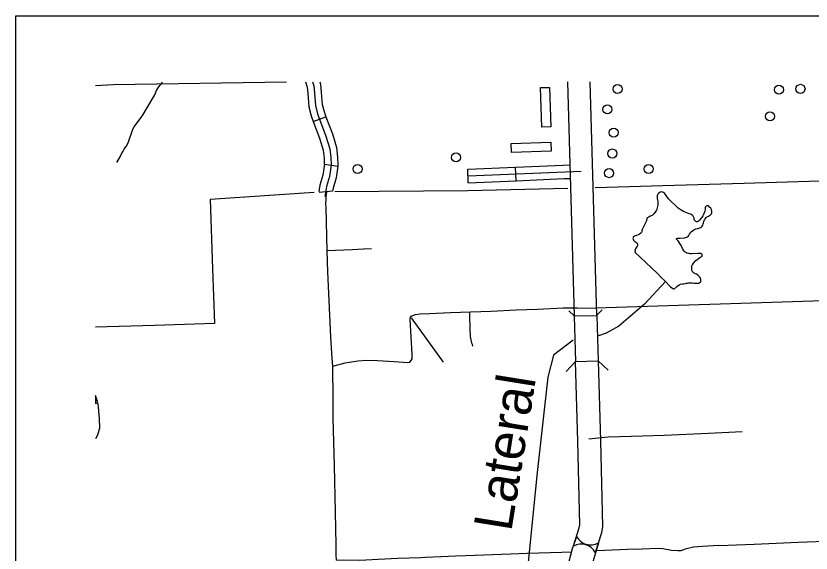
# Model space of a CAD drawing. Extents: x 309348 to 309445, y 336383 to 336484.
# Drawn here: x 309347.661 to 309349.42, y 336402.8 to 336403.988 of the extents above; entities that cross this region are included whole.
import ezdxf

# ---------------------------------------------------------------- set-up
doc = ezdxf.new("R2010")
doc.units = 0
doc.layers.add('R_Annotation', color=7, linetype='Continuous')
doc.layers.add('R_Border Notes', color=7, linetype='Continuous')

msp = doc.modelspace()

# ---------------------------------------------------------------- linework, layer by layer
at = {"layer": 'R_Annotation'}
for p, q in [((309348.3185, 336403.7542), (309348.3466, 336403.7647)), ((309348.343, 336403.6597), (309348.3727, 336403.6557)), ((309348.6615, 336403.619), (309348.6602, 336403.649)), ((309348.767, 336403.6235), (309348.7657, 336403.6535)), ((309348.8987, 336403.2237), (309348.9487, 336403.2252)), ((309348.9237, 336403.2245), (309348.9237, 336403.2245)), ((309347.8371, 336403.1491), (309347.8371, 336403.1312)), ((309347.8371, 336403.1312), (309347.8416, 336403.1322))]:
    msp.add_line(p, q, dxfattribs=at)
for points in [[(309347.8371, 336403.8341), (309347.8767, 336403.8358), (309348.2591, 336403.8418)], [(309347.8838, 336403.6635), (309347.8922, 336403.6776), (309347.8946, 336403.683), (309347.8976, 336403.689), (309347.9004, 336403.693), (309347.9043, 336403.6991), (309347.9088, 336403.707), (309347.9192, 336403.7374), (309347.9226, 336403.7422), (309347.9284, 336403.7506), (309347.9376, 336403.7631), (309347.9419, 336403.77), (309347.9495, 336403.7824), (309347.9678, 336403.813), (309347.9717, 336403.8227), (309347.9769, 336403.8308), (309347.9833, 336403.839), (309347.9849, 336403.8418)], [(309347.9675, 336403.8124), (309347.9678, 336403.813), (309347.9717, 336403.8227), (309347.9769, 336403.8308), (309347.9833, 336403.839), (309347.9849, 336403.8418)], [(309348.3012, 336403.8418), (309348.3052, 336403.8305), (309348.3061, 336403.8162), (309348.3084, 336403.7869), (309348.3137, 336403.767), (309348.3185, 336403.7542)], [(309348.3171, 336403.8418), (309348.32, 336403.8335), (309348.3211, 336403.8173), (309348.3233, 336403.7895), (309348.328, 336403.7716), (309348.3465, 336403.722), (309348.3549, 336403.6941), (309348.3573, 336403.6745), (309348.358, 336403.6587), (309348.3545, 336403.6327), (309348.3478, 336403.6105), (309348.3439, 336403.5885)], [(309348.333, 336403.8418), (309348.3348, 336403.8365), (309348.3361, 336403.8184), (309348.3381, 336403.792), (309348.3423, 336403.7762), (309348.3466, 336403.7647)], [(309348.8808, 336403.8418), (309348.8958, 336403.3245)], [(309348.8958, 336403.3245), (309348.9458, 336403.3254), (309348.9308, 336403.8418)], [(309347.9139, 336403.7219), (309347.9192, 336403.7374), (309347.9226, 336403.7422), (309347.9284, 336403.7506), (309347.9376, 336403.7631), (309347.9419, 336403.77), (309347.9495, 336403.7824), (309347.9539, 336403.7897)], [(309348.3185, 336403.7542), (309348.3323, 336403.7172), (309348.3402, 336403.691), (309348.3424, 336403.6733), (309348.3429, 336403.6594), (309348.343, 336403.6597)], [(309348.3466, 336403.7647), (309348.3607, 336403.7268), (309348.3696, 336403.6972), (309348.3723, 336403.6758), (309348.373, 336403.658), (309348.3727, 336403.6557)], [(309347.8838, 336403.6635), (309347.8922, 336403.6776), (309347.8946, 336403.683), (309347.8976, 336403.689), (309347.9004, 336403.693), (309347.9034, 336403.6978)], [(309348.343, 336403.6597), (309348.3398, 336403.6359), (309348.3332, 336403.614), (309348.3307, 336403.5997)], [(309348.3727, 336403.6557), (309348.3692, 336403.6295), (309348.3624, 336403.607), (309348.3613, 336403.6005), (309348.3312, 336403.5975)], [(309348.6602, 336403.649), (309348.7657, 336403.6535)], [(309348.6608, 336403.634), (309348.9113, 336403.6447)], [(309348.7657, 336403.6535), (309348.8713, 336403.658)], [(309348.8713, 336403.658), (309348.8861, 336403.6586)], [(309348.767, 336403.6235), (309348.8726, 336403.628)], [(309348.8726, 336403.628), (309348.887, 336403.6286)], [(309348.6615, 336403.619), (309348.767, 336403.6235)], [(309349.4462, 336403.3654), (309349.4444, 336403.4333), (309349.4412, 336403.5534), (309349.4393, 336403.6226), (309349.2716, 336403.6175), (309349.092, 336403.6121), (309348.9682, 336403.6083), (309348.9422, 336403.6077)], [(309348.3207, 336403.5975), (309348.0902, 336403.5816), (309348.0956, 336403.4288), (309348.0998, 336403.3076), (309347.9676, 336403.3038), (309347.8371, 336403.3)], [(309348.3493, 336403.4684), (309348.3469, 336403.5642), (309348.3466, 336403.5734), (309348.3468, 336403.5828), (309348.3469, 336403.587), (309348.3482, 336403.5992)], [(309348.8815, 336403.6063), (309348.6607, 336403.6013), (309348.3659, 336403.5991)], [(309349.1245, 336403.4962), (309349.13, 336403.4962), (309349.1396, 336403.4974), (309349.1444, 336403.4984), (309349.1468, 336403.4994), (309349.1481, 336403.5), (309349.1496, 336403.5021), (309349.1504, 336403.5038), (309349.1509, 336403.5054), (309349.152, 336403.5077), (309349.1532, 336403.5093), (309349.1546, 336403.5108), (309349.16, 336403.5148), (309349.1647, 336403.5172), (309349.1676, 336403.5179), (309349.1698, 336403.5182), (309349.1726, 336403.5194), (309349.175, 336403.5202), (309349.1772, 336403.5219), (309349.1786, 336403.5233), (309349.1799, 336403.5255), (309349.1811, 336403.5284), (309349.1816, 336403.5307), (309349.1826, 336403.5331), (309349.1841, 336403.5368), (309349.1856, 336403.5388), (309349.1872, 336403.5421), (309349.1889, 336403.5432), (309349.1897, 336403.5446), (309349.1927, 336403.5454), (309349.1951, 336403.5464), (309349.1965, 336403.5471), (309349.1982, 336403.5485), (309349.1992, 336403.5502), (309349.2, 336403.5522), (309349.2002, 336403.5537), (309349.2002, 336403.5564), (309349.1993, 336403.56), (309349.1978, 336403.5625), (309349.1958, 336403.564), (309349.1948, 336403.5652), (309349.1933, 336403.5671), (309349.1921, 336403.5679), (309349.1905, 336403.5683), (309349.1894, 336403.5681), (309349.1875, 336403.5671), (309349.1862, 336403.5661), (309349.1856, 336403.5639), (309349.1853, 336403.5622), (309349.1851, 336403.5593), (309349.1846, 336403.5563), (309349.1835, 336403.5525), (309349.1819, 336403.549), (309349.1801, 336403.5459), (309349.1779, 336403.5421), (309349.1764, 336403.5404), (309349.1731, 336403.536), (309349.1698, 336403.5333), (309349.1686, 336403.5331), (309349.1679, 336403.5328), (309349.1664, 336403.5328), (309349.165, 336403.5331), (309349.1635, 336403.5346), (309349.1618, 336403.5365), (309349.1613, 336403.5373), (309349.161, 336403.5409), (309349.159, 336403.5448), (309349.1568, 336403.5476), (309349.1537, 336403.5493), (309349.1502, 336403.5505), (309349.1449, 336403.5524), (309349.1375, 336403.5554), (309349.1304, 336403.5595), (309349.126, 336403.5628), (309349.1044, 336403.5831), (309349.0988, 336403.5911), (309349.0952, 336403.5956), (309349.0934, 336403.5973), (309349.0907, 336403.5985), (309349.0888, 336403.5987), (309349.0858, 336403.5978), (309349.0822, 336403.5955), (309349.0809, 336403.5938), (309349.0795, 336403.5901), (309349.0792, 336403.5879), (309349.0795, 336403.5841), (309349.0809, 336403.5772), (309349.0804, 336403.571), (309349.08, 336403.5662), (309349.0787, 336403.5608), (309349.0768, 336403.5566), (309349.0741, 336403.5529), (309349.0718, 336403.5502), (309349.0679, 336403.5463), (309349.0638, 336403.5453), (309349.0608, 336403.5432), (309349.0574, 336403.5414), (309349.0562, 336403.5393), (309349.0554, 336403.5356), (309349.055, 336403.5331), (309349.0484, 336403.5202)], [(309349.0484, 336403.5202), (309349.0457, 336403.5158), (309349.0451, 336403.5133), (309349.0451, 336403.5106), (309349.0444, 336403.5093), (309349.043, 336403.5079), (309349.0398, 336403.5054), (309349.0375, 336403.5042), (309349.0334, 336403.5025), (309349.0293, 336403.5008), (309349.0268, 336403.4996), (309349.026, 336403.4986), (309349.0258, 336403.4976), (309349.0256, 336403.4961), (309349.0258, 336403.4942), (309349.0268, 336403.492), (309349.0283, 336403.4903), (309349.0302, 336403.4888), (309349.0321, 336403.4873), (309349.0339, 336403.4859), (309349.0353, 336403.4846), (309349.0358, 336403.4839), (309349.0359, 336403.4829), (309349.0361, 336403.4819), (309349.0358, 336403.4803), (309349.0348, 336403.4787), (309349.0322, 336403.4741), (309349.0307, 336403.4707), (309349.0304, 336403.4694), (309349.0302, 336403.4682), (309349.0302, 336403.4675), (309349.0303, 336403.4666), (309349.0304, 336403.4659), (309349.0305, 336403.4655), (309349.0306, 336403.4653)], [(309349.1136, 336403.3855), (309349.1139, 336403.3853), (309349.1155, 336403.3847), (309349.116, 336403.3846), (309349.1171, 336403.3848), (309349.1182, 336403.3854), (309349.1197, 336403.387), (309349.1225, 336403.3895), (309349.1278, 336403.3933), (309349.1308, 336403.3948), (309349.1344, 336403.3953), (309349.1382, 336403.3955), (309349.142, 336403.3964), (309349.1436, 336403.3972), (309349.1456, 336403.3974), (309349.1475, 336403.3977), (309349.1495, 336403.3979), (309349.1503, 336403.3979), (309349.1528, 336403.398), (309349.1539, 336403.3979), (309349.1571, 336403.3979), (309349.1613, 336403.3972), (309349.1635, 336403.3967), (309349.166, 336403.3967), (309349.1677, 336403.3968), (309349.1693, 336403.3968), (309349.1713, 336403.3969), (309349.1725, 336403.3974), (309349.1738, 336403.3986), (309349.1751, 336403.3996), (309349.1758, 336403.4007), (309349.176, 336403.4022), (309349.176, 336403.4038), (309349.1757, 336403.4055), (309349.175, 336403.4074), (309349.1743, 336403.4093), (309349.1725, 336403.4121), (309349.1703, 336403.414), (309349.1662, 336403.4168), (309349.1643, 336403.4177), (309349.1614, 336403.4193), (309349.1604, 336403.4199), (309349.1592, 336403.4206), (309349.1582, 336403.4218), (309349.1577, 336403.4222), (309349.1574, 336403.4227), (309349.1566, 336403.4238), (309349.1562, 336403.4247), (309349.1558, 336403.4261), (309349.1556, 336403.4284), (309349.1558, 336403.4338), (309349.156, 336403.4351), (309349.1564, 336403.4365), (309349.1571, 336403.4379), (309349.1598, 336403.4415), (309349.1647, 336403.4468), (309349.1739, 336403.4541), (309349.1769, 336403.4554), (309349.1781, 336403.4566), (309349.1785, 336403.457), (309349.1788, 336403.4578), (309349.179, 336403.4583), (309349.179, 336403.4592), (309349.179, 336403.4599), (309349.1787, 336403.4607), (309349.1782, 336403.4612), (309349.1776, 336403.4617), (309349.177, 336403.4621), (309349.1764, 336403.4623), (309349.1753, 336403.4624), (309349.1734, 336403.4625), (309349.1692, 336403.4626), (309349.1562, 336403.4618), (309349.152, 336403.4619), (309349.1501, 336403.4623), (309349.1484, 336403.4624), (309349.1452, 336403.4636), (309349.1428, 336403.4645), (309349.1411, 336403.4656), (309349.14, 336403.4667), (309349.1374, 336403.4699), (309349.1353, 336403.4734), (309349.1336, 336403.477), (309349.1321, 336403.4802), (309349.1294, 336403.4845), (309349.1271, 336403.4885), (309349.1256, 336403.4904), (309349.1241, 336403.4918), (309349.1233, 336403.4925), (309349.1226, 336403.4933), (309349.1223, 336403.494), (309349.1219, 336403.4948), (309349.1221, 336403.4953), (309349.1223, 336403.4956), (309349.1229, 336403.496), (309349.1245, 336403.4962)], [(309348.4474, 336403.4728), (309348.4293, 336403.472), (309348.4045, 336403.471), (309348.3493, 336403.4684)], [(309348.3619, 336403.2139), (309348.3603, 336403.2306), (309348.357, 336403.2781), (309348.3504, 336403.4224), (309348.3493, 336403.4684)], [(309349.0306, 336403.4653), (309349.0307, 336403.4651)], [(309349.0307, 336403.4651), (309349.0539, 336403.4424), (309349.0808, 336403.4178), (309349.0871, 336403.4104), (309349.0952, 336403.4033), (309349.109, 336403.3887), (309349.1136, 336403.3855)], [(309349.0976, 336403.4008), (309349.0514, 336403.3505), (309348.9941, 336403.3023), (309348.9662, 336403.2869), (309348.9496, 336403.2808)], [(309348.9205, 336403.342), (309349.4473, 336403.3586)], [(309348.3619, 336403.2139), (309348.3892, 336403.2209), (309348.4168, 336403.2257), (309348.4372, 336403.227), (309348.4607, 336403.226), (309348.4977, 336403.2238), (309348.5278, 336403.2219), (309348.5319, 336403.2226), (309348.535, 336403.226), (309348.5375, 336403.2301), (309348.5375, 336403.24), (309348.5331, 336403.3164), (309348.5334, 336403.3222), (309348.5348, 336403.3241), (309348.5447, 336403.3275), (309348.5539, 336403.3292), (309348.5755, 336403.3302), (309348.6222, 336403.3319), (309348.6661, 336403.3336), (309348.7121, 336403.3348), (309348.7673, 336403.3379), (309348.8146, 336403.3396), (309348.871, 336403.3428), (309348.903, 336403.3423), (309348.9205, 336403.342)], [(309348.6717, 336403.2579), (309348.6705, 336403.2613), (309348.6695, 336403.2648), (309348.6686, 336403.2683), (309348.6678, 336403.2718), (309348.6672, 336403.2753), (309348.6666, 336403.2789), (309348.6662, 336403.2825), (309348.666, 336403.2861), (309348.6658, 336403.2897), (309348.6647, 336403.3322)], [(309348.8836, 336403.336), (309348.8958, 336403.3245)], [(309348.9458, 336403.326), (309348.9573, 336403.3381)], [(309348.6063, 336403.2225), (309348.5361, 336403.3206)], [(309348.8958, 336403.3242), (309348.8958, 336403.324)], [(309348.8958, 336403.3238), (309348.8987, 336403.2237)], [(309348.9458, 336403.3254), (309348.9487, 336403.2251)], [(309348.8937, 336403.271), (309348.8502, 336403.2378), (309348.8375, 336403.1892), (309348.8132, 336402.9721), (309348.7923, 336402.7651)], [(309348.8987, 336403.2237), (309348.8781, 336403.2019)], [(309348.8943, 336402.8162), (309348.907, 336402.8565), (309348.908, 336402.8629), (309348.9038, 336403.0474), (309348.8987, 336403.2237)], [(309348.9487, 336403.2252), (309348.9538, 336403.0487), (309348.9581, 336402.8596), (309348.9559, 336402.8454), (309348.9423, 336402.8021)], [(309348.9705, 336403.2046), (309348.9487, 336403.2252)], [(309348.3696, 336402.785), (309348.3693, 336402.7967), (309348.3689, 336402.8185), (309348.3677, 336402.8908), (309348.3655, 336402.9944), (309348.3628, 336403.0985), (309348.3624, 336403.1392), (309348.3619, 336403.2139)], [(309347.8416, 336403.1322), (309347.8403, 336403.1377), (309347.8371, 336403.1491)], [(309347.8418, 336403.1312), (309347.8449, 336403.098), (309347.8453, 336403.0768), (309347.8413, 336403.0609), (309347.8371, 336403.053)], [(309348.9283, 336403.0532), (309348.9708, 336403.0574), (309349.0226, 336403.0591), (309349.0947, 336403.0611), (309349.1925, 336403.0657), (309349.2671, 336403.0694)], [(309348.9492, 336402.8231), (309348.9292, 336402.7559), (309348.9286, 336402.7442), (309348.9315, 336402.6599), (309348.9311, 336402.5893), (309348.9504, 336402.0727), (309348.9004, 336402.0724), (309348.881, 336402.5884), (309348.8815, 336402.6591), (309348.8785, 336402.7447), (309348.8794, 336402.7627), (309348.8922, 336402.8107), (309348.9012, 336402.8372)], [(309349.216, 336402.8173), (309349.2938, 336402.8205), (309349.3912, 336402.8243), (309349.4698, 336402.8277), (309349.5013, 336402.8295), (309349.5261, 336402.8309), (309349.5512, 336402.8326), (309349.5879, 336402.8347), (309349.6414, 336402.837), (309349.6917, 336402.839), (309349.7466, 336402.8407), (309349.8185, 336402.843), (309349.8543, 336402.8442), (309349.891, 336402.8454), (309349.9124, 336402.8473)], [(309349.216, 336402.8173), (309349.1788, 336402.8153), (309349.1597, 336402.8136), (309349.1413, 336402.8089), (309349.1317, 336402.8058), (309349.1248, 336402.8055), (309349.1112, 336402.8063), (309349.0921, 336402.8098), (309349.0791, 336402.8104), (309349.0462, 336402.8095), (309349.0138, 336402.8087), (309348.9624, 336402.8061), (309348.9433, 336402.8054)], [(309348.3696, 336402.7849), (309348.3857, 336402.7856), (309348.4217, 336402.7847), (309348.4624, 336402.7869), (309348.5059, 336402.789), (309348.5563, 336402.7908), (309348.5664, 336402.7912), (309348.6005, 336402.7929), (309348.6328, 336402.7943), (309348.677, 336402.7961), (309348.7152, 336402.7975), (309348.7551, 336402.7986), (309348.7913, 336402.8), (309348.8684, 336402.8028), (309348.8903, 336402.8035)]]:
    msp.add_lwpolyline(points, dxfattribs=at)
for points in [[(309348.8213, 336403.8292), (309348.8413, 336403.8298), (309348.8439, 336403.7423), (309348.8239, 336403.7417)], [(309348.7573, 336403.6856), (309348.7566, 336403.7056), (309348.8441, 336403.7087), (309348.8448, 336403.6887)]]:
    msp.add_lwpolyline(points, close=True, dxfattribs=at)
for centre in [(309348.9916, 336403.8261), (309349.3485, 336403.8247), (309349.3963, 336403.8265), (309348.9693, 336403.7812), (309349.3287, 336403.7657), (309348.9831, 336403.7297), (309348.6344, 336403.6751), (309348.9802, 336403.6836), (309348.4164, 336403.6495), (309348.9729, 336403.6402), (309349.0604, 336403.6495)]:
    msp.add_circle(centre, 0.01, dxfattribs=at)
for centre, radius, start, end in [((309348.9319, 336402.8533), 0.0347, 207.6096, 299.7479), ((309348.9112, 336402.7848), 0.0356, 29.0401, 118.3175)]:
    msp.add_arc(centre, radius, start, end, dxfattribs=at)
at = {"layer": 'R_Border Notes'}
for p, q in [((309347.6607, 336403.9877), (309356.3641, 336403.9877)), ((309347.6607, 336395.7269), (309347.6607, 336403.9877))]:
    msp.add_line(p, q, dxfattribs=at)

# ---------------------------------------------------------------- texts
at = {"layer": 'R_Annotation'}
msp.add_text('Lateral', height=0.08451, rotation=80.8478, dxfattribs=at).set_placement((309348.7564, 336402.8462))

doc.saveas('drawing.dxf')
